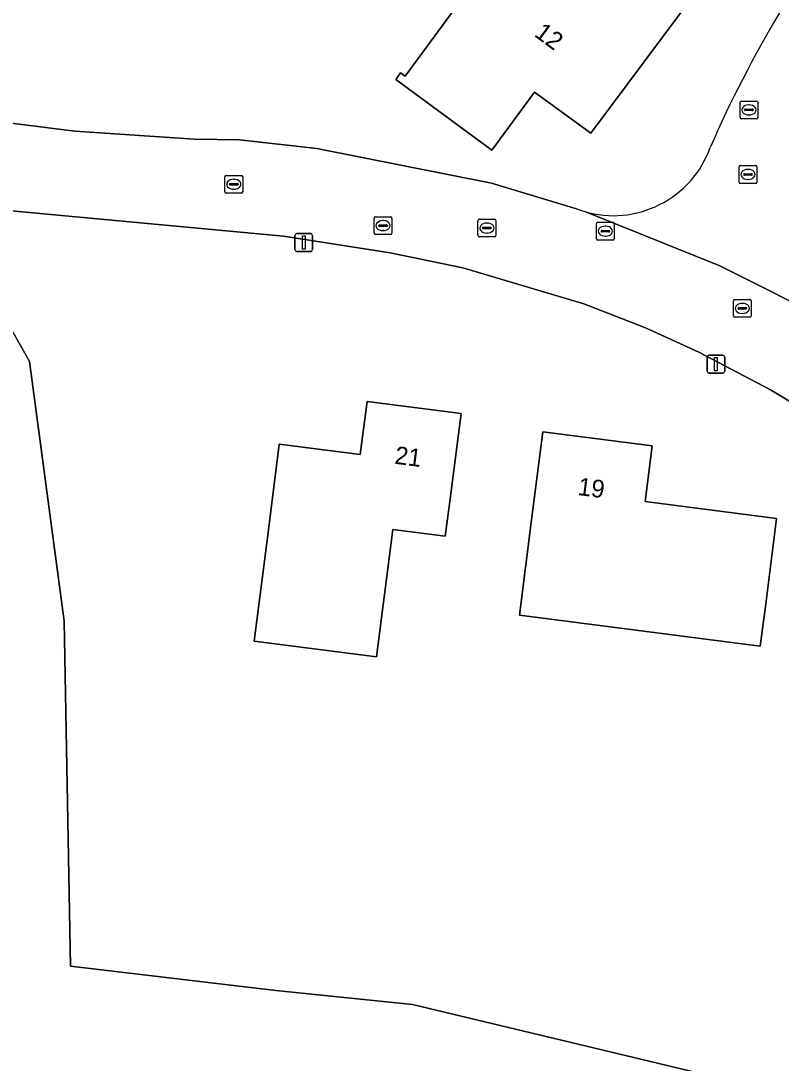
# Model space of a CAD drawing. Extents: x 163266 to 164362, y 381528 to 382286.
# Drawn here: x 163445.6 to 163488.3, y 381611.8 to 381670.5 of the extents above; entities that cross this region are included whole.
import ezdxf

# ---------------------------------------------------------------- set-up
doc = ezdxf.new("R2010")
doc.units = 0
for name, color, linetype in [('IMGEO_Brandkraan', 7, 'Continuous'), ('IMGEO_Erf', 7, 'Continuous'), ('IMGEO_Kolk', 7, 'Continuous'), ('IMGEO_Lichtmast', 7, 'Continuous'), ('IMGEO_Loofbos', 7, 'Continuous'), ('IMGEO_Pand', 7, 'Continuous'), ('IMGEO_Pand_nummerreeks', 7, 'Continuous'), ('IMGEO_Rijbaan_lokaal_open', 7, 'Continuous'), ('IMGEO_Rioolput', 7, 'Continuous')]:
    doc.layers.add(name, color=color, linetype=linetype)

msp = doc.modelspace()

# ---------------------------------------------------------------- linework, layer by layer
at = {"layer": 'IMGEO_Brandkraan'}
for p, q in [((163465.445, 381658.536), (163465.445, 381659.388)), ((163465.52, 381659.462), (163466.372, 381659.462)), ((163465.747, 381659.005), (163466.145, 381659.005)), ((163465.933, 381659.242), (163465.958, 381659.242)), ((163466.446, 381659.388), (163466.446, 381658.536)), ((163466.372, 381658.462), (163465.52, 381658.462)), ((163465.704, 381658.956), (163465.704, 381658.968)), ((163466.142, 381658.919), (163465.744, 381658.919)), ((163465.956, 381658.682), (163465.931, 381658.682)), ((163466.188, 381658.968), (163466.188, 381658.956))]:
    msp.add_line(p, q, dxfattribs=at)
for points in [[(163465.445, 381658.536), (163465.445, 381659.388)], [(163465.52, 381659.462), (163466.372, 381659.462)], [(163466.446, 381659.388), (163466.446, 381658.536)], [(163466.372, 381658.462), (163465.52, 381658.462)]]:
    msp.add_lwpolyline(points, dxfattribs=at)
for centre, radius, start, end in [((163465.522, 381659.386), 0.0765, 91.55205, 178.44795), ((163465.522, 381659.386), 0.0765, 91.55205, 178.44795), ((163465.744, 381658.965), 0.0403, 85.87752, 175.75265), ((163466.149, 381658.967), 0.0386, 1.73085, 96.63898), ((163466.37, 381659.386), 0.0765, 1.55205, 88.44795), ((163466.37, 381659.386), 0.0765, 1.55205, 88.44795), ((163465.522, 381658.538), 0.0765, 181.55205, 268.44795), ((163465.522, 381658.538), 0.0765, 181.55205, 268.44795), ((163465.741, 381658.955), 0.0366, 178.93798, 274.71019), ((163466.145, 381658.962), 0.043, 264.86636, 352.45326), ((163466.37, 381658.538), 0.0765, 271.55205, 358.44795), ((163466.37, 381658.538), 0.0765, 271.55205, 358.44795)]:
    msp.add_arc(centre, radius, start, end, dxfattribs=at)
for centre, major_axis, ratio, start_param, end_param in [((163465.932, 381658.962), (-0.387, 0.002), 0.722429, 4.712389, 7.853982), ((163465.957, 381658.962), (-0.39, 0.002), 0.717154, 1.570796, 4.712389)]:
    msp.add_ellipse(centre, major_axis=major_axis, ratio=ratio, start_param=start_param, end_param=end_param, dxfattribs=at)
at = {"layer": 'IMGEO_Erf'}
for points in [[(163466.896, 381677.957), (163469.578, 381681.64), (163466.822, 381683.646), (163468.386, 381685.794), (163471.141, 381683.788), (163481.831, 381676.005), (163479.738, 381673.13), (163482.71, 381670.966), (163477.628, 381664.153), (163474.473, 381666.471), (163472.073, 381663.204), (163466.657, 381667.183), (163466.93, 381667.554), (163467.179, 381667.37), (163471.668, 381673.479), (163471.749, 381673.42), (163473.532, 381672.835), (163474.954, 381674.791), (163472.04, 381676.909), (163470.761, 381675.149)], [(163469.443, 381641.485), (163466.489, 381641.865), (163465.568, 381634.704), (163458.685, 381635.589), (163459.472, 381641.705), (163460.108, 381646.663), (163464.658, 381646.079), (163465.043, 381649.074), (163470.331, 381648.394), (163469.695, 381643.436)], [(163480.688, 381643.441), (163488.089, 381642.489), (163487.453, 381637.531), (163487.166, 381635.306), (163473.612, 381637.048), (163474.301, 381642.408), (163474.938, 381647.367), (163481.091, 381646.576)]]:
    msp.add_lwpolyline(points, close=True, dxfattribs=at)
for points in [[(163442.176, 381665.079), (163448.608, 381664.27), (163455.329, 381663.829), (163457.86, 381663.79), (163462.224, 381663.302), (163472.048, 381661.348), (163476.829, 381659.912)], [(163494.209, 381645.839), (163487.738, 381649.717), (163483.709, 381651.834), (163480.719, 381653.221), (163477.242, 381654.553), (163470.435, 381656.592), (163466.34, 381657.437), (163460.334, 381658.369), (163442.602, 381660.009), (163441.974, 381658.511), (163446.05, 381651.319), (163447.993, 381636.708), (163448.357, 381617.306), (163459.913, 381615.932), (163467.608, 381615.147), (163500.109, 381607.374), (163500.96, 381607.171), (163500.848, 381606.174), (163534.27, 381588.252), (163555.584, 381575.614), (163562.99, 381579.592), (163569.593, 381582.28), (163569.528, 381582.82), (163567.957, 381586.195)]]:
    msp.add_lwpolyline(points, dxfattribs=at)
for centre, radius, start, end in [((163546.847, 381635.976), 68.235, 149.1904, 156.33561), ((163479.032, 381665.204), 5.627, 295.92199, 340.91259), ((163478.896, 381665.17), 5.65, 248.54299, 253.46737), ((163478.903, 381665.211), 5.691, 253.5129, 297.06026)]:
    msp.add_arc(centre, radius, start, end, dxfattribs=at)
at = {"layer": 'IMGEO_Kolk'}
for p, q in [((163485.977, 381661.414), (163485.977, 381662.266)), ((163486.052, 381662.34), (163486.904, 381662.34)), ((163486.465, 381662.12), (163486.49, 381662.12)), ((163486.978, 381662.266), (163486.978, 381661.414)), ((163457.045, 381660.862), (163457.045, 381661.714)), ((163457.12, 381661.788), (163457.972, 381661.788)), ((163457.533, 381661.568), (163457.558, 381661.568)), ((163458.046, 381661.714), (163458.046, 381660.862)), ((163486.236, 381661.834), (163486.236, 381661.846)), ((163486.674, 381661.797), (163486.276, 381661.797)), ((163486.279, 381661.883), (163486.677, 381661.883)), ((163486.488, 381661.56), (163486.463, 381661.56)), ((163486.72, 381661.846), (163486.72, 381661.834)), ((163457.972, 381660.788), (163457.12, 381660.788)), ((163457.304, 381661.282), (163457.304, 381661.294)), ((163457.742, 381661.245), (163457.344, 381661.245)), ((163457.347, 381661.331), (163457.745, 381661.331)), ((163457.556, 381661.008), (163457.531, 381661.008)), ((163457.788, 381661.294), (163457.788, 381661.282)), ((163486.904, 381661.34), (163486.052, 381661.34)), ((163471.286, 381658.399), (163471.286, 381659.251)), ((163471.361, 381659.325), (163472.213, 381659.325)), ((163471.774, 381659.105), (163471.799, 381659.105)), ((163472.287, 381659.251), (163472.287, 381658.399)), ((163471.545, 381658.819), (163471.545, 381658.831)), ((163471.983, 381658.782), (163471.585, 381658.782)), ((163471.588, 381658.868), (163471.986, 381658.868)), ((163471.797, 381658.545), (163471.772, 381658.545)), ((163472.029, 381658.831), (163472.029, 381658.819)), ((163472.213, 381658.325), (163471.361, 381658.325)), ((163485.657, 381653.879), (163485.657, 381654.731)), ((163485.732, 381654.805), (163486.584, 381654.805)), ((163485.916, 381654.299), (163485.916, 381654.311)), ((163485.959, 381654.348), (163486.357, 381654.348)), ((163486.145, 381654.585), (163486.17, 381654.585)), ((163486.4, 381654.311), (163486.4, 381654.299)), ((163486.658, 381654.731), (163486.658, 381653.879)), ((163486.584, 381653.805), (163485.732, 381653.805)), ((163486.354, 381654.262), (163485.956, 381654.262)), ((163486.168, 381654.025), (163486.143, 381654.025))]:
    msp.add_line(p, q, dxfattribs=at)
for points in [[(163485.977, 381661.414), (163485.977, 381662.266)], [(163486.052, 381662.34), (163486.904, 381662.34)], [(163486.978, 381662.266), (163486.978, 381661.414)], [(163457.045, 381660.862), (163457.045, 381661.714)], [(163457.12, 381661.788), (163457.972, 381661.788)], [(163458.046, 381661.714), (163458.046, 381660.862)], [(163457.972, 381660.788), (163457.12, 381660.788)], [(163486.904, 381661.34), (163486.052, 381661.34)], [(163471.286, 381658.399), (163471.286, 381659.251)], [(163471.361, 381659.325), (163472.213, 381659.325)], [(163472.287, 381659.251), (163472.287, 381658.399)], [(163472.213, 381658.325), (163471.361, 381658.325)], [(163485.657, 381653.879), (163485.657, 381654.731)], [(163485.732, 381654.805), (163486.584, 381654.805)], [(163486.658, 381654.731), (163486.658, 381653.879)], [(163486.584, 381653.805), (163485.732, 381653.805)]]:
    msp.add_lwpolyline(points, dxfattribs=at)
for centre, radius, start, end in [((163486.054, 381662.264), 0.0765, 91.55205, 178.44795), ((163486.054, 381662.264), 0.0765, 91.55205, 178.44795), ((163486.902, 381662.264), 0.0765, 1.55205, 88.44795), ((163486.902, 381662.264), 0.0765, 1.55205, 88.44795), ((163457.122, 381661.712), 0.0765, 91.55205, 178.44795), ((163457.122, 381661.712), 0.0765, 91.55205, 178.44795), ((163457.97, 381661.712), 0.0765, 1.55205, 88.44795), ((163457.97, 381661.712), 0.0765, 1.55205, 88.44795), ((163486.054, 381661.416), 0.0765, 181.55205, 268.44795), ((163486.054, 381661.416), 0.0765, 181.55205, 268.44795), ((163486.276, 381661.843), 0.0403, 85.87752, 175.75265), ((163486.273, 381661.833), 0.0366, 178.93798, 274.71019), ((163486.677, 381661.84), 0.043, 264.86636, 352.45326), ((163486.681, 381661.845), 0.0386, 1.73085, 96.63898), ((163486.902, 381661.416), 0.0765, 271.55205, 358.44795), ((163486.902, 381661.416), 0.0765, 271.55205, 358.44795), ((163457.122, 381660.864), 0.0765, 181.55205, 268.44795), ((163457.122, 381660.864), 0.0765, 181.55205, 268.44795), ((163457.344, 381661.291), 0.0403, 85.87752, 175.75265), ((163457.341, 381661.281), 0.0366, 178.93798, 274.71019), ((163457.745, 381661.288), 0.043, 264.86636, 352.45326), ((163457.749, 381661.293), 0.0386, 1.73085, 96.63898), ((163457.97, 381660.864), 0.0765, 271.55205, 358.44795), ((163457.97, 381660.864), 0.0765, 271.55205, 358.44795), ((163471.363, 381659.249), 0.0765, 91.55205, 178.44795), ((163471.363, 381659.249), 0.0765, 91.55205, 178.44795), ((163472.211, 381659.249), 0.0765, 1.55205, 88.44795), ((163472.211, 381659.249), 0.0765, 1.55205, 88.44795), ((163471.585, 381658.828), 0.0403, 85.87752, 175.75265), ((163471.582, 381658.818), 0.0366, 178.93798, 274.71019), ((163471.986, 381658.825), 0.043, 264.86636, 352.45326), ((163471.99, 381658.83), 0.0386, 1.73085, 96.63898), ((163471.363, 381658.401), 0.0765, 181.55205, 268.44795), ((163471.363, 381658.401), 0.0765, 181.55205, 268.44795), ((163472.211, 381658.401), 0.0765, 271.55205, 358.44795), ((163472.211, 381658.401), 0.0765, 271.55205, 358.44795), ((163485.734, 381654.729), 0.0765, 91.55205, 178.44795), ((163485.734, 381654.729), 0.0765, 91.55205, 178.44795), ((163485.956, 381654.308), 0.0403, 85.87752, 175.75265), ((163486.361, 381654.31), 0.0386, 1.73085, 96.63898), ((163486.582, 381654.729), 0.0765, 1.55205, 88.44795), ((163486.582, 381654.729), 0.0765, 1.55205, 88.44795), ((163485.734, 381653.881), 0.0765, 181.55205, 268.44795), ((163485.734, 381653.881), 0.0765, 181.55205, 268.44795), ((163485.953, 381654.298), 0.0366, 178.93798, 274.71019), ((163486.357, 381654.305), 0.043, 264.86636, 352.45326), ((163486.582, 381653.881), 0.0765, 271.55205, 358.44795), ((163486.582, 381653.881), 0.0765, 271.55205, 358.44795)]:
    msp.add_arc(centre, radius, start, end, dxfattribs=at)
for centre, major_axis, ratio, start_param, end_param in [((163486.464, 381661.84), (-0.387, 0.002), 0.722429, 4.712389, 7.853982), ((163486.489, 381661.84), (-0.39, 0.002), 0.717154, 1.570796, 4.712389), ((163457.532, 381661.288), (-0.387, 0.002), 0.722429, 4.712389, 7.853982), ((163457.557, 381661.288), (-0.39, 0.002), 0.717154, 1.570796, 4.712389), ((163471.773, 381658.825), (-0.387, 0.002), 0.722429, 4.712389, 7.853982), ((163471.798, 381658.825), (-0.39, 0.002), 0.717154, 1.570796, 4.712389), ((163486.144, 381654.305), (-0.387, 0.002), 0.722429, 4.712389, 7.853982), ((163486.169, 381654.305), (-0.39, 0.002), 0.717154, 1.570796, 4.712389)]:
    msp.add_ellipse(centre, major_axis=major_axis, ratio=ratio, start_param=start_param, end_param=end_param, dxfattribs=at)
at = {"layer": 'IMGEO_Lichtmast'}
for p, q in [((163461.084, 381658.51), (163461.874, 381658.51)), ((163461.874, 381658.51), (163461.084, 381658.51)), ((163460.984, 381657.61), (163460.984, 381658.41)), ((163460.984, 381658.41), (163460.984, 381657.61)), ((163461.974, 381658.41), (163461.974, 381657.61)), ((163461.974, 381657.61), (163461.974, 381658.41)), ((163461.874, 381657.51), (163461.084, 381657.51)), ((163461.084, 381657.51), (163461.874, 381657.51)), ((163484.175, 381650.767), (163484.175, 381651.567)), ((163484.175, 381651.567), (163484.175, 381650.767)), ((163484.275, 381651.667), (163485.065, 381651.667)), ((163485.065, 381651.667), (163484.275, 381651.667)), ((163485.165, 381651.567), (163485.165, 381650.767)), ((163485.165, 381650.767), (163485.165, 381651.567)), ((163485.065, 381650.667), (163484.275, 381650.667)), ((163484.275, 381650.667), (163485.065, 381650.667))]:
    msp.add_line(p, q, dxfattribs=at)
for points in [[(163461.404, 381658.385), (163461.554, 381658.385), (163461.554, 381657.635), (163461.404, 381657.635), (163461.404, 381658.385)], [(163484.595, 381651.542), (163484.745, 381651.542), (163484.745, 381650.792), (163484.595, 381650.792), (163484.595, 381651.542)]]:
    msp.add_lwpolyline(points, dxfattribs=at)
for centre, start, end in [((163461.084, 381658.41), 90, 180), ((163461.084, 381658.41), 90, 180), ((163461.874, 381658.41), 0, 90), ((163461.874, 381658.41), 360, 90), ((163461.084, 381657.61), 180, 270), ((163461.084, 381657.61), 180, 270), ((163461.874, 381657.61), 270, 0), ((163461.874, 381657.61), 270, 0), ((163484.275, 381651.567), 90, 180), ((163484.275, 381651.567), 90, 180), ((163485.065, 381651.567), 0, 90), ((163485.065, 381651.567), 360, 90), ((163484.275, 381650.767), 180, 270), ((163484.275, 381650.767), 180, 270), ((163485.065, 381650.767), 270, 0), ((163485.065, 381650.767), 270, 0)]:
    msp.add_arc(centre, 0.1, start, end, dxfattribs=at)
at = {"layer": 'IMGEO_Loofbos'}
msp.add_lwpolyline([(163437.361, 381555.035), (163449.037, 381576.049), (163452.51, 381582.299), (163459.767, 381578.313), (163468.82, 381594.735), (163472.507, 381601.424), (163497.938, 381587.999), (163500, 381584.158), (163509.284, 381566.862), (163508.679, 381566.604), (163511.885, 381560.366), (163517.317, 381558.716), (163518.903, 381558.234), (163555.584, 381575.614), (163534.27, 381588.252), (163500.848, 381606.174), (163500.96, 381607.171), (163500.109, 381607.374), (163467.608, 381615.147), (163459.913, 381615.932), (163448.357, 381617.306), (163447.993, 381636.708), (163446.05, 381651.319), (163441.974, 381658.511)], dxfattribs=at)
at = {"layer": 'IMGEO_Pand'}
for points in [[(163482.71, 381670.966), (163479.738, 381673.13), (163481.831, 381676.005), (163471.141, 381683.788), (163469.578, 381681.64), (163466.896, 381677.957), (163470.761, 381675.149), (163472.04, 381676.909), (163474.954, 381674.791), (163473.532, 381672.835), (163471.749, 381673.42), (163471.668, 381673.479), (163467.179, 381667.37), (163466.93, 381667.554), (163466.657, 381667.183), (163472.073, 381663.204), (163474.473, 381666.471), (163477.628, 381664.153)], [(163469.695, 381643.436), (163470.331, 381648.394), (163465.043, 381649.074), (163464.658, 381646.079), (163460.108, 381646.663), (163459.472, 381641.705), (163458.685, 381635.589), (163465.568, 381634.704), (163466.489, 381641.865), (163469.443, 381641.485)], [(163487.453, 381637.531), (163488.089, 381642.489), (163480.688, 381643.441), (163481.091, 381646.576), (163474.938, 381647.367), (163474.301, 381642.408), (163473.612, 381637.048), (163487.166, 381635.306)]]:
    msp.add_lwpolyline(points, close=True, dxfattribs=at)
at = {"layer": 'IMGEO_Rijbaan_lokaal_open'}
for points in [[(163476.829, 381659.912), (163472.048, 381661.348), (163462.224, 381663.302), (163457.86, 381663.79), (163455.329, 381663.829), (163448.608, 381664.27), (163442.176, 381665.079), (163437.182, 381666.013), (163436.031, 381661.135), (163437.328, 381660.841), (163442.602, 381660.009), (163460.334, 381658.369), (163466.34, 381657.437), (163470.435, 381656.592), (163477.242, 381654.553), (163480.719, 381653.221), (163483.709, 381651.834), (163487.738, 381649.717), (163494.209, 381645.839)], [(163491.371, 381653.46), (163484.894, 381656.697), (163477.288, 381659.754)], [(163477.288, 381659.754), (163484.894, 381656.697), (163491.371, 381653.46)]]:
    msp.add_lwpolyline(points, dxfattribs=at)
for centre, radius, start, end in [((163546.847, 381635.976), 68.235, 149.1904, 156.33561), ((163479.032, 381665.204), 5.627, 295.92199, 340.91259), ((163478.896, 381665.17), 5.65, 248.54299, 253.46737), ((163478.903, 381665.211), 5.691, 253.5129, 297.06026)]:
    msp.add_arc(centre, radius, start, end, dxfattribs=at)
at = {"layer": 'IMGEO_Rioolput'}
for p, q in [((163486.03, 381665.045), (163486.03, 381665.897)), ((163486.105, 381665.971), (163486.957, 381665.971)), ((163486.289, 381665.465), (163486.289, 381665.477)), ((163486.332, 381665.514), (163486.73, 381665.514)), ((163486.518, 381665.751), (163486.543, 381665.751)), ((163486.773, 381665.477), (163486.773, 381665.465)), ((163487.031, 381665.897), (163487.031, 381665.045)), ((163486.957, 381664.971), (163486.105, 381664.971)), ((163486.727, 381665.428), (163486.329, 381665.428)), ((163486.541, 381665.191), (163486.516, 381665.191)), ((163477.954, 381658.223), (163477.954, 381659.075)), ((163478.029, 381659.149), (163478.881, 381659.149)), ((163478.955, 381659.075), (163478.955, 381658.223)), ((163478.213, 381658.643), (163478.213, 381658.655)), ((163478.651, 381658.606), (163478.253, 381658.606)), ((163478.256, 381658.692), (163478.654, 381658.692)), ((163478.442, 381658.929), (163478.467, 381658.929)), ((163478.697, 381658.655), (163478.697, 381658.643)), ((163478.881, 381658.149), (163478.029, 381658.149)), ((163478.465, 381658.369), (163478.44, 381658.369))]:
    msp.add_line(p, q, dxfattribs=at)
for points in [[(163486.03, 381665.045), (163486.03, 381665.897)], [(163486.105, 381665.971), (163486.957, 381665.971)], [(163487.031, 381665.897), (163487.031, 381665.045)], [(163486.957, 381664.971), (163486.105, 381664.971)], [(163477.954, 381658.223), (163477.954, 381659.075)], [(163478.029, 381659.149), (163478.881, 381659.149)], [(163478.955, 381659.075), (163478.955, 381658.223)], [(163478.881, 381658.149), (163478.029, 381658.149)]]:
    msp.add_lwpolyline(points, dxfattribs=at)
for centre, radius, start, end in [((163486.107, 381665.895), 0.0765, 91.55205, 178.44795), ((163486.107, 381665.895), 0.0765, 91.55205, 178.44795), ((163486.329, 381665.474), 0.0403, 85.87752, 175.75265), ((163486.326, 381665.464), 0.0366, 178.93798, 274.71019), ((163486.73, 381665.471), 0.043, 264.86636, 352.45326), ((163486.734, 381665.476), 0.0386, 1.73085, 96.63898), ((163486.955, 381665.895), 0.0765, 1.55205, 88.44795), ((163486.955, 381665.895), 0.0765, 1.55205, 88.44795), ((163486.107, 381665.047), 0.0765, 181.55205, 268.44795), ((163486.107, 381665.047), 0.0765, 181.55205, 268.44795), ((163486.955, 381665.047), 0.0765, 271.55205, 358.44795), ((163486.955, 381665.047), 0.0765, 271.55205, 358.44795), ((163478.031, 381659.073), 0.0765, 91.55205, 178.44795), ((163478.031, 381659.073), 0.0765, 91.55205, 178.44795), ((163478.879, 381659.073), 0.0765, 1.55205, 88.44795), ((163478.879, 381659.073), 0.0765, 1.55205, 88.44795), ((163478.253, 381658.652), 0.0403, 85.87752, 175.75265), ((163478.25, 381658.642), 0.0366, 178.93798, 274.71019), ((163478.654, 381658.649), 0.043, 264.86636, 352.45326), ((163478.658, 381658.654), 0.0386, 1.73085, 96.63898), ((163478.031, 381658.225), 0.0765, 181.55205, 268.44795), ((163478.031, 381658.225), 0.0765, 181.55205, 268.44795), ((163478.879, 381658.225), 0.0765, 271.55205, 358.44795), ((163478.879, 381658.225), 0.0765, 271.55205, 358.44795)]:
    msp.add_arc(centre, radius, start, end, dxfattribs=at)
for centre, major_axis, ratio, start_param, end_param in [((163486.517, 381665.471), (-0.387, 0.002), 0.722429, 4.712389, 7.853982), ((163486.542, 381665.471), (-0.39, 0.002), 0.717154, 1.570796, 4.712389), ((163478.441, 381658.649), (-0.387, 0.002), 0.722429, 4.712389, 7.853982), ((163478.466, 381658.649), (-0.39, 0.002), 0.717154, 1.570796, 4.712389)]:
    msp.add_ellipse(centre, major_axis=major_axis, ratio=ratio, start_param=start_param, end_param=end_param, dxfattribs=at)

# ---------------------------------------------------------------- texts
at = {"layer": 'IMGEO_Pand_nummerreeks'}
for s, rotation, p in [('12', 323.69739, (163474.397, 381669.653)), ('21', 352.67237, (163466.561, 381645.572)), ('19', 352.67451, (163476.867, 381643.812))]:
    msp.add_text(s, height=1, rotation=rotation, dxfattribs=at).set_placement(p)

doc.saveas('drawing.dxf')
